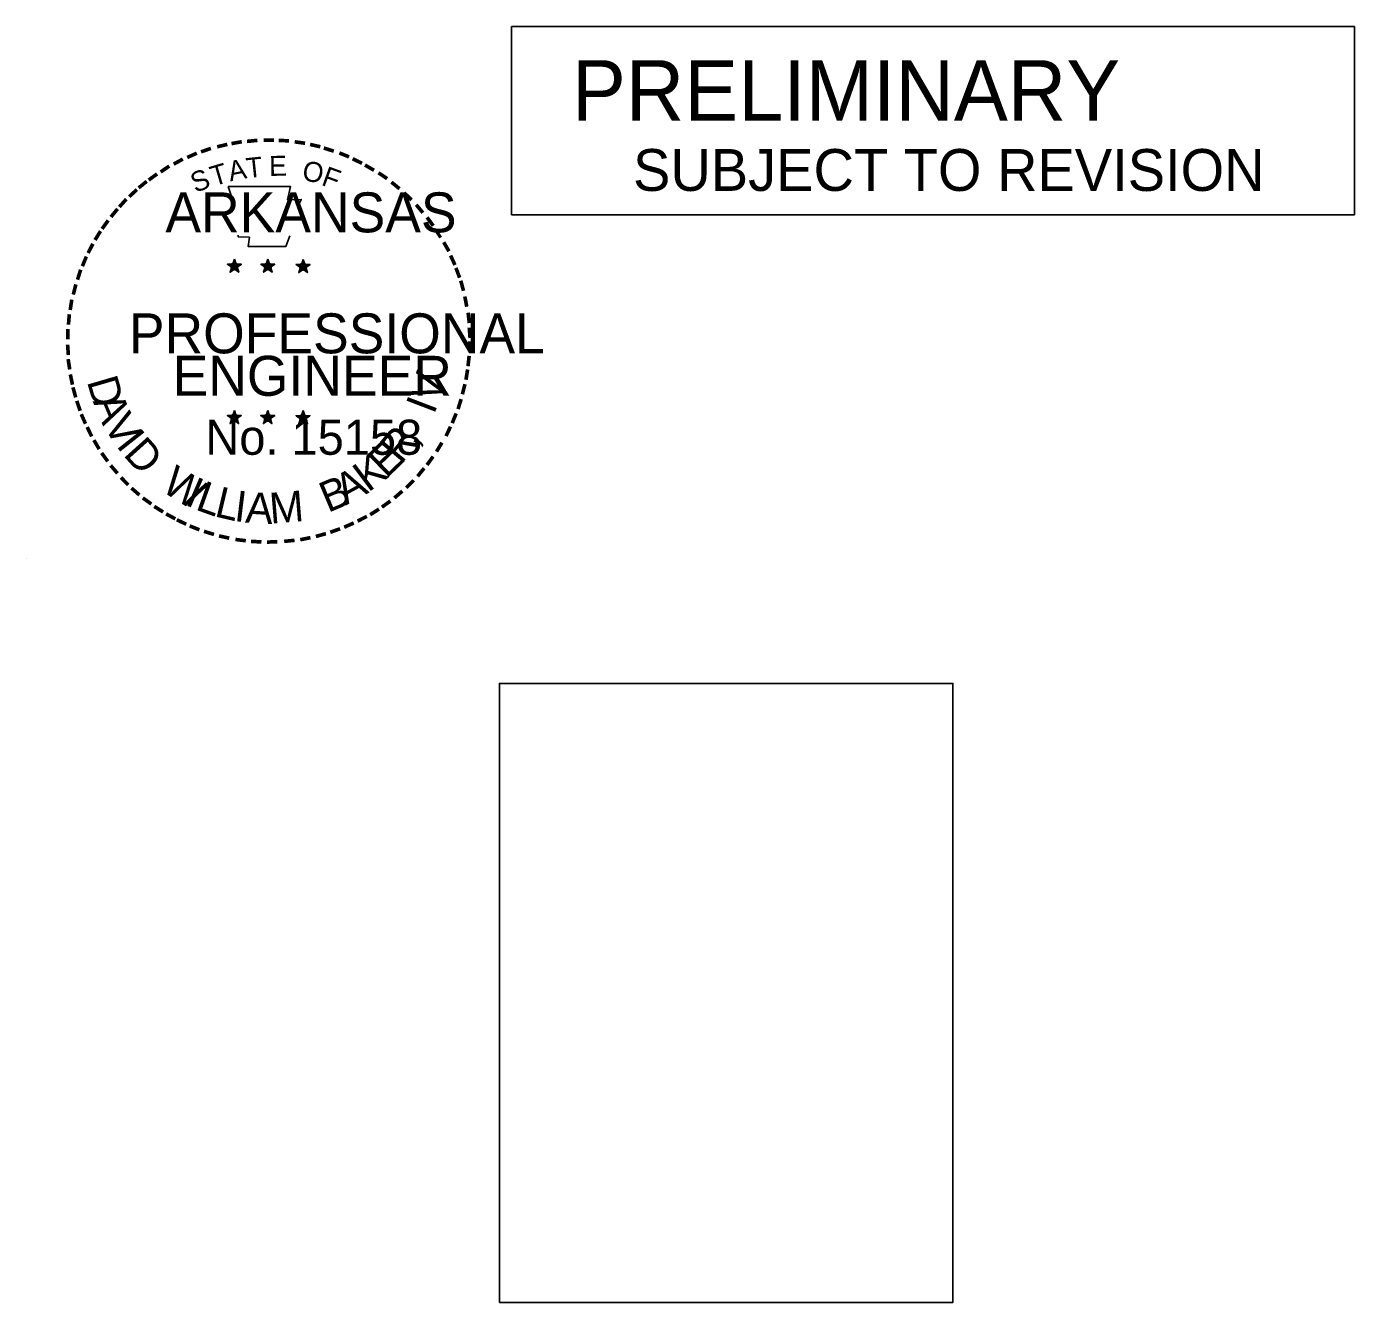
# Model space of a CAD drawing. Extents: x 0 to 1.72, y 0 to 0.98.
# Drawn here: x 1.4339 to 1.7194, y 0.602 to 0.8763 of the extents above; entities that cross this region are included whole.
import ezdxf

# ---------------------------------------------------------------- set-up
doc = ezdxf.new("R2010")
doc.units = 0
for name, color, linetype in [('R_Border PE', 7, 'Continuous'), ('R_No Plot', 7, 'Continuous'), ('SHET_Stamp-Prelim', 7, 'Continuous'), ('SHET_Stamp-Seal', 7, 'Continuous')]:
    doc.layers.add(name, color=color, linetype=linetype)

msp = doc.modelspace()

# ---------------------------------------------------------------- linework, layer by layer
at = {"layer": 'R_Border PE'}
for p, q in [((1.47714, 0.8252), (1.47863, 0.82473)), ((1.47714, 0.8252), (1.47822, 0.82501)), ((1.47714, 0.8252), (1.47815, 0.82468)), ((1.47863, 0.8263), (1.47846, 0.82521)), ((1.47863, 0.82473), (1.47863, 0.8263)), ((1.47863, 0.8263), (1.47885, 0.82522)), ((1.48013, 0.8252), (1.47863, 0.82473)), ((1.48013, 0.8252), (1.4789, 0.82499)), ((1.48013, 0.8252), (1.47925, 0.82477)), ((1.48431, 0.8252), (1.48581, 0.82473)), ((1.48431, 0.8252), (1.4854, 0.82501)), ((1.48431, 0.8252), (1.48533, 0.82468)), ((1.48581, 0.8263), (1.48563, 0.82521)), ((1.48581, 0.82473), (1.48581, 0.8263)), ((1.48581, 0.8263), (1.48602, 0.82522)), ((1.4873, 0.8252), (1.48581, 0.82473)), ((1.4873, 0.8252), (1.48607, 0.82499)), ((1.4873, 0.8252), (1.48643, 0.82477)), ((1.49189, 0.82515), (1.49339, 0.82468)), ((1.49189, 0.82515), (1.49298, 0.82496)), ((1.49189, 0.82515), (1.49291, 0.82463)), ((1.49339, 0.82624), (1.49321, 0.82516)), ((1.49339, 0.82468), (1.49339, 0.82624)), ((1.49339, 0.82624), (1.4936, 0.82517)), ((1.49488, 0.82515), (1.49339, 0.82468)), ((1.49488, 0.82515), (1.49365, 0.82494)), ((1.49488, 0.82515), (1.494, 0.82471)), ((1.47771, 0.82345), (1.47863, 0.82473)), ((1.47771, 0.82345), (1.47825, 0.8245)), ((1.47771, 0.82345), (1.47863, 0.82438)), ((1.47955, 0.82345), (1.47863, 0.82473)), ((1.47955, 0.82345), (1.47863, 0.82437)), ((1.47955, 0.82345), (1.47896, 0.8247)), ((1.48488, 0.82345), (1.48581, 0.82473)), ((1.48488, 0.82345), (1.48542, 0.8245)), ((1.48488, 0.82345), (1.4858, 0.82438)), ((1.48673, 0.82345), (1.4858, 0.82437)), ((1.48673, 0.82345), (1.48581, 0.82473)), ((1.48673, 0.82345), (1.48614, 0.8247)), ((1.49246, 0.8234), (1.49339, 0.82468)), ((1.49246, 0.8234), (1.493, 0.82445)), ((1.49246, 0.8234), (1.49338, 0.82433)), ((1.49431, 0.8234), (1.49338, 0.82432)), ((1.49431, 0.8234), (1.49339, 0.82468)), ((1.49431, 0.8234), (1.49372, 0.82465)), ((1.47862, 0.79376), (1.47844, 0.79267)), ((1.47862, 0.79219), (1.47862, 0.79376)), ((1.47862, 0.79376), (1.47883, 0.79268)), ((1.48579, 0.79376), (1.48561, 0.79267)), ((1.48579, 0.79219), (1.48579, 0.79376)), ((1.48579, 0.79376), (1.486, 0.79268)), ((1.49338, 0.79371), (1.49321, 0.79263)), ((1.49338, 0.79214), (1.49338, 0.79371)), ((1.49338, 0.79371), (1.49359, 0.79264)), ((1.47712, 0.79266), (1.47862, 0.79219)), ((1.47712, 0.79266), (1.47821, 0.79247)), ((1.47712, 0.79266), (1.47814, 0.79214)), ((1.47769, 0.79091), (1.47862, 0.79219)), ((1.47769, 0.79091), (1.47823, 0.79196)), ((1.47769, 0.79091), (1.47861, 0.79184)), ((1.47953, 0.79091), (1.47861, 0.79183)), ((1.48011, 0.79266), (1.47862, 0.79219)), ((1.47953, 0.79091), (1.47862, 0.79219)), ((1.48011, 0.79266), (1.47888, 0.79245)), ((1.47953, 0.79091), (1.47894, 0.79216)), ((1.48011, 0.79266), (1.47923, 0.79223)), ((1.48429, 0.79266), (1.48579, 0.79219)), ((1.48429, 0.79266), (1.48538, 0.79247)), ((1.48429, 0.79266), (1.48531, 0.79214)), ((1.48486, 0.79091), (1.48579, 0.79219)), ((1.48486, 0.79091), (1.4854, 0.79196)), ((1.48486, 0.79091), (1.48578, 0.79184)), ((1.4867, 0.79091), (1.48578, 0.79183)), ((1.48728, 0.79266), (1.48579, 0.79219)), ((1.4867, 0.79091), (1.48579, 0.79219)), ((1.48728, 0.79266), (1.48605, 0.79245)), ((1.4867, 0.79091), (1.48612, 0.79216)), ((1.48728, 0.79266), (1.4864, 0.79223)), ((1.49188, 0.79262), (1.49338, 0.79214)), ((1.49188, 0.79262), (1.49297, 0.79243)), ((1.49188, 0.79262), (1.4929, 0.7921)), ((1.49245, 0.79087), (1.49338, 0.79214)), ((1.49245, 0.79087), (1.493, 0.79192)), ((1.49245, 0.79087), (1.49337, 0.7918)), ((1.4943, 0.79087), (1.49337, 0.79179)), ((1.49487, 0.79262), (1.49338, 0.79214)), ((1.4943, 0.79087), (1.49338, 0.79214)), ((1.49487, 0.79262), (1.49364, 0.79241)), ((1.4943, 0.79087), (1.49371, 0.79212)), ((1.49487, 0.79262), (1.494, 0.79218))]:
    msp.add_line(p, q, dxfattribs=at)
for points in [[(1.47731, 0.84187), (1.47847, 0.83831)], [(1.4924, 0.83791), (1.49301, 0.83913), (1.49006, 0.83902), (1.4907, 0.84187), (1.47731, 0.84187)], [(1.47943, 0.83146), (1.47943, 0.83108), (1.48184, 0.831), (1.48161, 0.82897), (1.48965, 0.82897), (1.49051, 0.83127)], [(1.47863, 0.8263), (1.47955, 0.82345), (1.47714, 0.8252), (1.48013, 0.8252), (1.47771, 0.82345), (1.47863, 0.8263)], [(1.48581, 0.8263), (1.48673, 0.82345), (1.48431, 0.8252), (1.4873, 0.8252), (1.48488, 0.82345), (1.48581, 0.8263)], [(1.49339, 0.82624), (1.49431, 0.8234), (1.49189, 0.82515), (1.49488, 0.82515), (1.49246, 0.8234), (1.49339, 0.82624)], [(1.47862, 0.79376), (1.47953, 0.79091), (1.47712, 0.79266), (1.48011, 0.79266), (1.47769, 0.79091), (1.47862, 0.79376)], [(1.48579, 0.79376), (1.4867, 0.79091), (1.48429, 0.79266), (1.48728, 0.79266), (1.48486, 0.79091), (1.48579, 0.79376)], [(1.49338, 0.79371), (1.4943, 0.79087), (1.49188, 0.79262), (1.49487, 0.79262), (1.49245, 0.79087), (1.49338, 0.79371)]]:
    msp.add_lwpolyline(points, dxfattribs=at)
for centre, radius in [((1.47863, 0.82472), 0.00074), ((1.47863, 0.82472), 0.000621), ((1.47863, 0.82472), 0.000497), ((1.47863, 0.82472), 0.000426), ((1.47863, 0.82472), 0.000321), ((1.47863, 0.82472), 0.000213), ((1.48581, 0.82472), 0.00074), ((1.48581, 0.82472), 0.000621), ((1.48581, 0.82472), 0.000497), ((1.48581, 0.82472), 0.000426), ((1.48581, 0.82472), 0.000321), ((1.48581, 0.82472), 0.000213), ((1.49339, 0.82467), 0.00074), ((1.49339, 0.82467), 0.000621), ((1.49339, 0.82467), 0.000497), ((1.49339, 0.82467), 0.000426), ((1.49339, 0.82467), 0.000321), ((1.49339, 0.82467), 0.000213), ((1.47863, 0.82472), 0.000127), ((1.48581, 0.82472), 0.000127), ((1.49339, 0.82467), 0.000127), ((1.47861, 0.79218), 0.00074), ((1.47861, 0.79218), 0.000621), ((1.47861, 0.79218), 0.000497), ((1.47861, 0.79218), 0.000426), ((1.47861, 0.79218), 0.000321), ((1.47861, 0.79218), 0.000213), ((1.47861, 0.79218), 0.000127), ((1.48578, 0.79218), 0.00074), ((1.48578, 0.79218), 0.000621), ((1.48578, 0.79218), 0.000497), ((1.48578, 0.79218), 0.000426), ((1.48578, 0.79218), 0.000321), ((1.48578, 0.79218), 0.000213), ((1.48578, 0.79218), 0.000127), ((1.49338, 0.79214), 0.00074), ((1.49338, 0.79214), 0.000621), ((1.49338, 0.79214), 0.000497), ((1.49338, 0.79214), 0.000426), ((1.49338, 0.79214), 0.000321), ((1.49338, 0.79214), 0.000213), ((1.49338, 0.79214), 0.000127)]:
    msp.add_circle(centre, radius, dxfattribs=at)
at = {"layer": 'R_No Plot'}
msp.add_line((1.43395, 0.76199), (1.43395, 0.76199), dxfattribs=at)
at = {"layer": 'SHET_Stamp-Prelim'}
msp.add_lwpolyline([(1.5382, 0.83584), (1.71937, 0.83584), (1.71937, 0.87629), (1.5382, 0.87629)], close=True, dxfattribs=at)
at = {"layer": 'SHET_Stamp-Seal'}
msp.add_lwpolyline([(1.53557, 0.60197), (1.63307, 0.60197), (1.63307, 0.73507), (1.53557, 0.73507)], close=True, dxfattribs=at)

# ---------------------------------------------------------------- texts
at = {"layer": 'R_Border PE'}
for s, height, rotation, p in [('-', 0.00688, 13.6302, (1.47515, 0.84775)), ('-', 0.00688, 10.2193, (1.47807, 0.84844)), ('-', 0.00688, 5.8968, (1.4812, 0.84891)), ('-', 0.00687, 0.1862, (1.48452, 0.84922)), ('-', 0.00687, 357.743, (1.48762, 0.84917)), ('-', 0.00688, 352.1617, (1.49082, 0.84893)), ('-', 0.00688, 347.2049, (1.49391, 0.84844)), ('-', 0.00687, 28.7918, (1.46649, 0.84419)), ('-', 0.00688, 24.3072, (1.46921, 0.84555)), ('-', 0.00687, 19.1761, (1.47193, 0.84671)), ('T', 0.0043, 6.0228, (1.48137, 0.8437)), ('E', 0.0043, 0.8323, (1.48611, 0.84417)), ('-', 0.00688, 342.3362, (1.49664, 0.84777)), ('-', 0.00688, 337.8551, (1.4998, 0.84681)), ('-', 0.00688, 334.1211, (1.50251, 0.84565)), ('-', 0.00688, 36.2317, (1.46144, 0.8409)), ('-', 0.00688, 34.0636, (1.46392, 0.8426)), ('S', 0.0043, 21.594, (1.47024, 0.84048)), ('T', 0.0043, 16.4036, (1.47417, 0.84191)), ('A', 0.0043, 11.2132, (1.47772, 0.84298)), ('O', 0.0043, 350.4515, (1.49301, 0.84327)), ('F', 0.0043, 340.0707, (1.49711, 0.84229)), ('-', 0.00688, 329.6409, (1.505, 0.84443)), ('-', 0.00688, 325.8627, (1.50776, 0.84288)), ('-', 0.00687, 38.9507, (1.45939, 0.83928)), ('-', 0.00688, 320.5297, (1.51038, 0.84105)), ('-', 0.00688, 48.423, (1.45561, 0.83543)), ('-', 0.00688, 42.9622, (1.45753, 0.83749)), ('-', 0.00688, 315.5786, (1.51295, 0.83895)), ('-', 0.00688, 50.6142, (1.45388, 0.83335)), ('-', 0.00687, 309.8797, (1.5154, 0.83659)), ('-', 0.00688, 54.2325, (1.4521, 0.83091)), ('-', 0.00688, 306.6522, (1.51765, 0.834)), ('-', 0.00687, 58.0706, (1.4507, 0.82865)), ('-', 0.00602, 303.6753, (1.51974, 0.83156)), ('-', 0.00688, 62.8713, (1.44936, 0.82601)), ('-', 0.00688, 299.6684, (1.52111, 0.82896)), ('-', 0.00687, 67.7743, (1.44825, 0.82338)), ('-', 0.00688, 294.6628, (1.52251, 0.82633)), ('-', 0.00688, 72.3945, (1.44731, 0.82068)), ('-', 0.00688, 290.5728, (1.52361, 0.82385)), ('-', 0.00688, 75.461, (1.44646, 0.81761)), ('-', 0.00688, 285.1233, (1.52461, 0.82135)), ('-', 0.00688, 81.2013, (1.44589, 0.81454)), ('-', 0.00688, 280.5493, (1.52547, 0.81817)), ('-', 0.00688, 85.1863, (1.44557, 0.81157)), ('-', 0.00688, 276.5962, (1.52617, 0.81487)), ('-', 0.00688, 89.0622, (1.44546, 0.80856)), ('-', 0.00688, 274.3301, (1.52643, 0.81176)), ('-', 0.00687, 94.1959, (1.44561, 0.80545)), ('-', 0.00688, 269.9407, (1.52657, 0.80905)), ('-', 0.00688, 263.5172, (1.52649, 0.80619)), ('-', 0.00688, 98.9479, (1.44592, 0.80258)), ('V', 0.00662, 72.6573, (1.52247, 0.79504)), ('-', 0.00688, 260.9953, (1.52619, 0.80338)), ('-', 0.00688, 101.7149, (1.4465, 0.79943)), ('D', 0.00662, 286.2848, (1.44688, 0.80003)), ('-', 0.00688, 255.7626, (1.52571, 0.80046)), ('-', 0.00688, 105.4578, (1.44719, 0.79687)), ('I', 0.00662, 69.0301, (1.52152, 0.79272)), ('-', 0.00688, 109.0874, (1.44812, 0.79416)), ('A', 0.00662, 292.7835, (1.44814, 0.79572)), ('V', 0.00662, 300.7936, (1.45034, 0.79065)), ('-', 0.00688, 252.8681, (1.52494, 0.79737)), ('-', 0.00687, 114.0643, (1.44921, 0.7916)), ('-', 0.00688, 247.8887, (1.52398, 0.79448)), ('-', 0.00688, 115.7289, (1.45052, 0.78895)), ('I', 0.00662, 308.3502, (1.45306, 0.7862)), ('D', 0.00662, 311.9774, (1.45456, 0.7842)), ('R', 0.00662, 50.3651, (1.51442, 0.78203)), (',', 0.00662, 57.4684, (1.51753, 0.78582)), ('-', 0.00687, 244.6197, (1.52285, 0.79177)), ('-', 0.00687, 120.4471, (1.45205, 0.78643)), ('E', 0.00662, 44.0175, (1.51127, 0.77899)), ('-', 0.00687, 239.0712, (1.52116, 0.78854)), ('-', 0.00688, 125.8934, (1.45379, 0.78402)), ('-', 0.00688, 130.7181, (1.45577, 0.78165)), ('W', 0.00662, 328.0731, (1.46263, 0.77661)), ('K', 0.00662, 36.9143, (1.50737, 0.77602)), ('-', 0.00688, 233.8452, (1.51943, 0.78574)), ('-', 0.00688, 134.2238, (1.45799, 0.7793)), ('I', 0.00662, 336.6877, (1.46774, 0.77356)), ('B', 0.00662, 22.8589, (1.49871, 0.77168)), ('A', 0.00662, 28.9042, (1.50256, 0.77329)), ('-', 0.00687, 231.2538, (1.51759, 0.78331)), ('-', 0.00688, 138.9338, (1.46025, 0.77731)), ('L', 0.00662, 340.3149, (1.47001, 0.77251)), ('L', 0.00662, 346.6625, (1.47413, 0.77103)), ('I', 0.00662, 353.0101, (1.4784, 0.77001)), ('M', 0.00662, 4.6473, (1.4864, 0.76939)), ('-', 0.00688, 221.0851, (1.51328, 0.77869)), ('-', 0.00687, 225.7653, (1.51553, 0.78088)), ('-', 0.00688, 144.6463, (1.46264, 0.77557)), ('A', 0.00662, 356.6373, (1.48087, 0.76965)), ('-', 0.00688, 215.7363, (1.51093, 0.77667)), ('-', 0.00688, 148.0898, (1.46505, 0.77397)), ('-', 0.00687, 151.5704, (1.46754, 0.77258)), ('-', 0.00687, 207.3568, (1.50623, 0.77352)), ('-', 0.00688, 212.2491, (1.50863, 0.775)), ('-', 0.00688, 154.6002, (1.46978, 0.77151)), ('-', 0.00688, 158.5612, (1.47246, 0.77042)), ('-', 0.00688, 162.7983, (1.47541, 0.76951)), ('-', 0.00688, 199.4643, (1.50084, 0.77095)), ('-', 0.00688, 204.2516, (1.50355, 0.77215)), ('-', 0.00688, 167.5555, (1.47848, 0.7688)), ('-', 0.00688, 173.1155, (1.4818, 0.76833)), ('-', 0.00688, 176.5183, (1.48501, 0.7681)), ('-', 0.00688, 181.5918, (1.48821, 0.76818)), ('-', 0.00687, 185.8167, (1.49169, 0.76851)), ('-', 0.00687, 191.2858, (1.49485, 0.76908)), ('-', 0.00688, 195.4743, (1.49798, 0.76993))]:
    msp.add_text(s, height=height, rotation=rotation, dxfattribs=at).set_placement(p)
for s, height, p in [('ARKANSAS', 0.008594, (1.46379, 0.83204)), ('PROFESSIONAL', 0.0085938, (1.45594, 0.80603)), ('ENGINEER', 0.008594, (1.46534, 0.7969)), ('No. 15158', 0.00755, (1.47239, 0.78422)), ('AAMU', 0.0000000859, (1.4855, 0.76937))]:
    msp.add_text(s, height=height, dxfattribs=at).set_placement(p)
at = {"layer": 'SHET_Stamp-Prelim'}
for s, height, p in [('PRELIMINARY', 0.013, (1.55117, 0.85606)), ('SUBJECT TO REVISION', 0.009, (1.56431, 0.84095))]:
    msp.add_text(s, height=height, dxfattribs=at).set_placement(p)

doc.saveas('drawing.dxf')
